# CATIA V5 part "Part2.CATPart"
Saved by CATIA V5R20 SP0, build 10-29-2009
Part number: Part2
Bounding box of the stored display mesh (mm): x 0 to 40, y 165 to 185, z 70 to 90
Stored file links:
  C:\Users\Ehsan Fathi\Desktop\Part2.CATPart
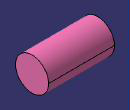
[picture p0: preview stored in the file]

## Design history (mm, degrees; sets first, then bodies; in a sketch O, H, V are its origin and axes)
Body1 (main body)
  DatumSurface1
  DatumCurve1
  Sketch1 on face of DatumSurface1, origin (10, 0, 0), H (0, 1, 0), V (0, 0, 1)
    projected circle E1 centre (175, 80) radius 10 from edge of DatumCurve1
  Pad1: profile Sketch1, direction (1, 0, 0), length 30, opposite side length 10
